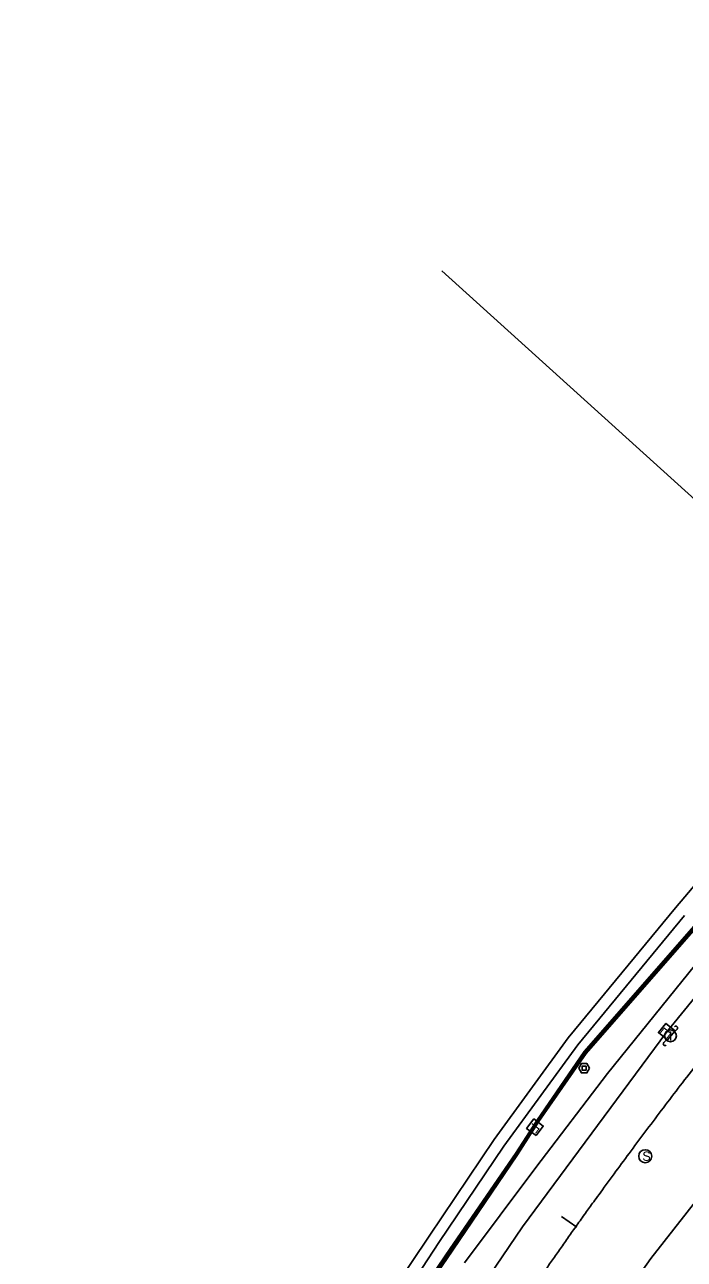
# Model space of a CAD drawing. Extents: x 1991878 to 2008544, y 770238 to 1141211.
# Drawn here: x 2007784 to 2008063, y 1139262 to 1139785 of the extents above; entities that cross this region are included whole.
import ezdxf

# ---------------------------------------------------------------- set-up
doc = ezdxf.new("R2010")
doc.units = 0
for name, color, linetype in [('RD_EX_SU_Elec', 7, 'Continuous'), ('RD_EX_SU_Gas', 7, 'Continuous'), ('RD_EX_SU_H2O', 7, 'Continuous'), ('RD_EX_SU_Pole', 7, 'Continuous'), ('RD_EX_SU_Sewer', 7, 'Continuous'), ('RD_EX_SU_SwpLmt', 7, 'Continuous'), ('RD_EX_SU_Telecom', 7, 'Continuous'), ('RD_HC_Cl', 7, 'Continuous')]:
    doc.layers.add(name, color=color, linetype=linetype)

msp = doc.modelspace()

# ---------------------------------------------------------------- linework, layer by layer
at = {"layer": 'RD_EX_SU_Elec'}
for points in [[(2008343.6, 1139562.26), (2008380.32, 1139598.68), (2008425.97, 1139646.35), (2008371.23, 1139696.87), (2008253.32, 1139579.8), (2008186.59, 1139509.23), (2008114.35, 1139431), (2008055.21, 1139358.58), (2007994.21, 1139276.04), (2007935.15, 1139188.81), (2007828.1, 1139009.37), (2007792.89, 1138934.82)], [(2008062.76, 1139407.73), (2008017.56, 1139352.95), (2007986.28, 1139310.11), (2007958.9, 1139269.34), (2007928.57, 1139223.01)]]:
    msp.add_lwpolyline(points, dxfattribs=at)
msp.add_lwpolyline([(2008055.59, 1139355.06), (2008058.73, 1139358.95), (2008054.84, 1139362.09), (2008051.7, 1139358.2)], close=True, dxfattribs=at)
at = {"layer": 'RD_EX_SU_Gas'}
msp.add_lwpolyline([(2008404.55, 1139750.7), (2008403.44, 1139749.58), (2008398.9, 1139744.83), (2008391.94, 1139734.83), (2008385.92, 1139728.82), (2008369.04, 1139711.9), (2008334.96, 1139675.4), (2008301.61, 1139643.32), (2008270.11, 1139611.37), (2008232.47, 1139573.05), (2008197.32, 1139535.98), (2008163.44, 1139498.28), (2008127.84, 1139456.99), (2008097.18, 1139422.1), (2008075.86, 1139397.4), (2008030.23, 1139340.85), (2007999.81, 1139301.13), (2007969.65, 1139260.73)], dxfattribs=at)
at = {"layer": 'RD_EX_SU_H2O'}
msp.add_lwpolyline([(2008019.12, 1139221.08), (2008048.48, 1139262.65), (2008073.58, 1139294.58), (2008079.22, 1139302.23), (2008110.71, 1139341.71), (2008143.34, 1139380.24), (2008168.92, 1139408.5), (2008210.81, 1139454.91), (2008245.96, 1139491.17), (2008281.21, 1139525.55), (2008316.14, 1139560.25), (2008351.07, 1139595.92), (2008385.58, 1139632.4), (2008419.77, 1139669.26), (2008455.08, 1139706.22), (2008458.85, 1139710.23), (2008459.45, 1139710.87)], dxfattribs=at)
at = {"layer": 'RD_EX_SU_Pole'}
for p, q in [((2008059.61, 1139359.63), (2008058.55, 1139358.57)), ((2008055.02, 1139355.03), (2008053.96, 1139353.97))]:
    msp.add_line(p, q, dxfattribs=at)
msp.add_circle((2008056.79, 1139356.8), 2.5, dxfattribs=at)
for centre, start, end in [((2008059.08, 1139360.16), 315, 135), ((2008054.49, 1139353.44), 135, 315)]:
    msp.add_arc(centre, 0.75, start, end, dxfattribs=at)
at = {"layer": 'RD_EX_SU_Sewer'}
for points in [[(2008022.59, 1139343.1), (2008021.44, 1139345.1), (2008019.13, 1139345.1), (2008017.98, 1139343.1), (2008019.13, 1139341.1), (2008021.44, 1139341.1)], [(2008021.1, 1139343.92), (2008019.47, 1139343.92), (2008019.47, 1139342.29), (2008021.1, 1139342.29)]]:
    msp.add_lwpolyline(points, close=True, dxfattribs=at)
msp.add_circle((2008046.12, 1139305.9), 2.75, dxfattribs=at)
at = {"layer": 'RD_EX_SU_SwpLmt'}
msp.add_lwpolyline([(2008308.62, 1139692.22), (2008303.98, 1139673.05), (2008302.61, 1139671.39), (2008217.14, 1139586.99), (2008146.65, 1139513.91), (2008110.85, 1139472.17), (2008058.97, 1139410.99), (2008013.6, 1139356.01), (2007982.19, 1139312.98), (2007954.73, 1139272.11), (2007894.74, 1139182.48), (2007866.63, 1139138.23), (2007843.93, 1139094.78), (2007785.35, 1138986.79)], dxfattribs=at)
msp.add_arc((2009858.48, 1137910.13), 2230.75, 135.28907, 163.89519, dxfattribs=at)
at = {"layer": 'RD_EX_SU_Telecom'}
for points in [[(2008305.4, 1139658.27), (2008303.69, 1139657.15), (2008296.15, 1139648.2), (2008264.57, 1139616.22), (2008225.94, 1139578.68), (2008191.19, 1139541.83), (2008155.65, 1139504.96), (2008121.25, 1139463.29), (2008090.5, 1139429.06), (2008067.62, 1139404.3), (2008020.3, 1139350.24), (2008000.26, 1139321.01), (2007991.22, 1139306.98), (2007963.62, 1139266.78), (2007931.75, 1139219.86)], [(2008305.4, 1139658.27), (2008304.18, 1139656.84), (2008296.58, 1139647.74), (2008264.95, 1139615.87), (2008226.45, 1139578.22), (2008191.55, 1139541.46), (2008156.07, 1139504.61), (2008121.74, 1139462.81), (2008090.98, 1139428.65), (2008068.11, 1139403.96), (2008020.75, 1139349.83), (2008000.71, 1139320.77), (2007991.64, 1139306.71), (2007964.15, 1139266.38), (2007932.21, 1139219.57)], [(2008305.4, 1139658.27), (2008304.81, 1139656.42), (2008297.07, 1139647.18), (2008265.35, 1139615.32), (2008226.85, 1139577.83), (2008191.88, 1139541.09), (2008156.34, 1139504.22), (2008122.19, 1139462.43), (2008091.39, 1139428.14), (2008068.51, 1139403.49), (2008021.17, 1139349.41), (2008001.14, 1139320.51), (2007992.13, 1139306.45), (2007964.8, 1139266.15), (2007932.81, 1139219.12)]]:
    msp.add_lwpolyline(points, dxfattribs=at)
msp.add_lwpolyline([(2007999.95, 1139314.64), (2008002.99, 1139318.61), (2007999.02, 1139321.65), (2007995.98, 1139317.68)], close=True, dxfattribs=at)
at = {"layer": 'RD_HC_Cl'}
for p, q in [((2007960.14, 1139680.51), (2008408.6, 1139274.45)), ((2008010.65, 1139280.44), (2008017.18, 1139275.82))]:
    msp.add_line(p, q, dxfattribs=at)
msp.add_open_spline([(2008468.44, 1139784.65), (2008330.54, 1139636.27), (2008112.04, 1139402.61), (2008010.65, 1139269.99), (2007954.96, 1139181.47), (2007845.36, 1139006.33), (2007807.05, 1138915.36), (2007714.1, 1138721), (2007657.93, 1138535.69), (2007584.82, 1138278.81), (2007557.24, 1138105.93), (2007524.47, 1137887.62), (2007511.86, 1137606.6), (2007518.19, 1137380.97), (2007535.52, 1137158.14), (2007573, 1136960.76), (2007648.83, 1136694.4), (2007817.41, 1136298.79), (2008044.24, 1135795.68), (2008373.08, 1135014.28)], degree=2, dxfattribs=at)

# ---------------------------------------------------------------- texts
at = {"layer": 'RD_EX_SU_Elec'}
msp.add_text('E', height=4, rotation=231.0931, dxfattribs=at).set_placement((2008054.42, 1139360.78))
at = {"layer": 'RD_EX_SU_Pole'}
msp.add_text('L', height=4, rotation=180, dxfattribs=at).set_placement((2008057.6, 1139358.73))
at = {"layer": 'RD_EX_SU_Sewer'}
msp.add_text('S', height=3.93, dxfattribs=at).set_placement((2008044.91, 1139303.93))
at = {"layer": 'RD_EX_SU_Telecom'}
msp.add_text('F', height=4, rotation=232.5545, dxfattribs=at).set_placement((2007998.59, 1139320.26))

doc.saveas('drawing.dxf')
